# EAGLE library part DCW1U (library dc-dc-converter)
DC-DC CONVERTER
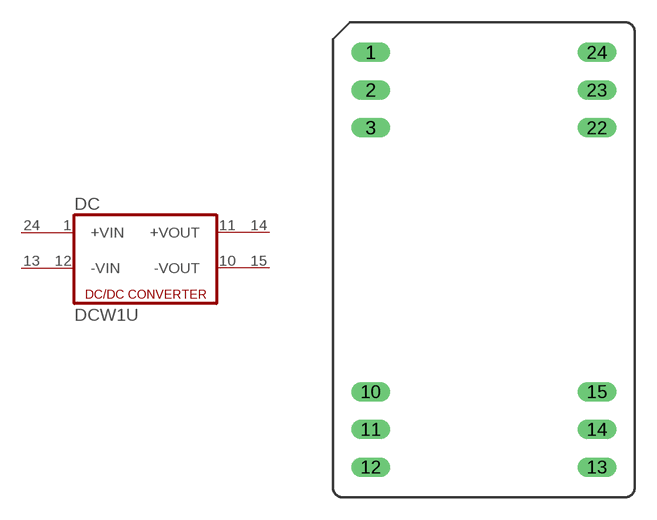
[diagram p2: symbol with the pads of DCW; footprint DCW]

Designator prefix DC

## DCW1U (OC_FARNELL: unknown; OC_NEWARK: unknown)  [DCW]
1  +VIN  pas
10  -VOUT  pas
11  +VOUT  pas
12  -VIN  pas
13  -VIN1  pas
14  +VOUT1  pas
15  -VOUT1  pas
24  +VIN1  pas

## Footprint DCW (pad centres in mm)
DC-DC CONVERTER
drill 0.813 long: 1 -7.62,13.97; 2 -7.62,11.43; 3 -7.62,8.89; 10 -7.62,-8.89; 11 -7.62,-11.43; 12 -7.62,-13.97; 13 7.62,-13.97; 14 7.62,-11.43; 15 7.62,-8.89; 22 7.62,8.89; 23 7.62,11.43; 24 7.62,13.97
